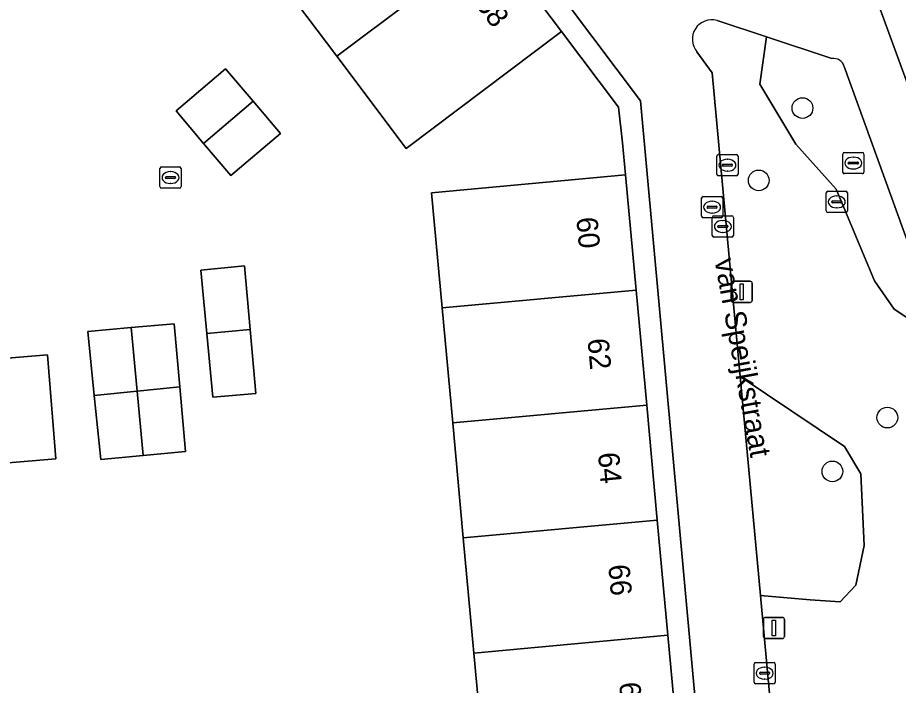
# Model space of a CAD drawing. Extents: x 160377 to 161131, y 383938 to 384853.
# Drawn here: x 160622.12 to 160663.69, y 384535.5 to 384567.01 of the extents above; entities that cross this region are included whole.
import ezdxf

# ---------------------------------------------------------------- set-up
doc = ezdxf.new("R2010")
doc.units = 0
for name, color, linetype in [('IMGEO_Boom', 7, 'Continuous'), ('IMGEO_Erf', 7, 'Continuous'), ('IMGEO_Groenvoorziening', 7, 'Continuous'), ('IMGEO_Kolk', 7, 'Continuous'), ('IMGEO_Lichtmast', 7, 'Continuous'), ('IMGEO_Openbare_ruimte_label', 7, 'Continuous'), ('IMGEO_Pand', 7, 'Continuous'), ('IMGEO_Pand_nummerreeks', 7, 'Continuous'), ('IMGEO_Rioolput', 7, 'Continuous'), ('IMGEO_Voetgangersgebied_open', 7, 'Continuous')]:
    doc.layers.add(name, color=color, linetype=linetype)

msp = doc.modelspace()

# ---------------------------------------------------------------- linework, layer by layer
at = {"layer": 'IMGEO_Boom'}
for centre in [(160659.166, 384562.744), (160657.1, 384559.33), (160663.171, 384548.138), (160660.578, 384545.599)]:
    msp.add_circle(centre, 0.489, dxfattribs=at)
at = {"layer": 'IMGEO_Erf'}
for points in [[(160656.048, 384504.315), (160656.893, 384504.376), (160651.516, 384563.083), (160634.758, 384585.358), (160611.972, 384615.646), (160608.482, 384613.028), (160596.383, 384603.983), (160593.555, 384601.453), (160592.642, 384600.679), (160589.954, 384598.377), (160589.048, 384597.617), (160586.272, 384595.285), (160585.368, 384594.478), (160578.674, 384588.862), (160588.469, 384577.392), (160609.42, 384552.826), (160611.199, 384533.452), (160614.226, 384500.488)], [(160742.043, 384557.929), (160741.675, 384559.771), (160712.316, 384578.736), (160711.06, 384579.547), (160690.284, 384592.968), (160678.608, 384600.475), (160670.645, 384605.594), (160652.047, 384589.687), (160648.865, 384586.974), (160652.625, 384581.692), (160662.829, 384567.417), (160665.29, 384560.709), (160670.064, 384547.52), (160670.583, 384546.086), (160681.057, 384517.15), (160682.984, 384507.279), (160717.593, 384514.044), (160723.481, 384515.195), (160749.399, 384520.262)], [(160629.603, 384562.612), (160631.936, 384564.59), (160633.234, 384563.069), (160634.532, 384561.547), (160632.184, 384559.557), (160630.9, 384561.077)], [(160631.054, 384552.1), (160630.774, 384555.098), (160632.834, 384555.303), (160633.101, 384552.29), (160633.369, 384549.277), (160631.333, 384549.101)], [(160627.479, 384552.382), (160629.508, 384552.567), (160629.776, 384549.584), (160630.051, 384546.531), (160628.049, 384546.342), (160626.047, 384546.153), (160625.741, 384549.174), (160625.434, 384552.196)]]:
    msp.add_lwpolyline(points, close=True, dxfattribs=at)
for points in [[(160621.611, 384601.175), (160624.884, 384596.822), (160628.157, 384592.469), (160631.431, 384588.116), (160634.704, 384583.762), (160637.977, 384579.409), (160641.25, 384575.056), (160644.524, 384570.703), (160647.791, 384566.349), (160650.487, 384562.787), (160650.671, 384561.096), (160650.813, 384559.589), (160651.313, 384554.154), (160651.813, 384548.726), (160652.312, 384543.297), (160652.811, 384537.869), (160653.311, 384532.44)], [(160644.155, 384531.6), (160643.656, 384537.028), (160643.158, 384542.457), (160642.659, 384547.885), (160642.161, 384553.314), (160641.662, 384558.742), (160650.813, 384559.589), (160650.671, 384561.096), (160650.487, 384562.787), (160647.791, 384566.349), (160640.461, 384560.832), (160637.187, 384565.185), (160633.913, 384569.537), (160630.639, 384573.89), (160627.365, 384578.243), (160624.091, 384582.595), (160620.818, 384586.948)], [(160619.944, 384550.806), (160623.524, 384551.103), (160623.931, 384546.19), (160620.351, 384545.893)]]:
    msp.add_lwpolyline(points, dxfattribs=at)
at = {"layer": 'IMGEO_Groenvoorziening'}
for points in [[(160657.46, 384566.101), (160655.132, 384566.872)], [(160674.853, 384526.804), (160665.84, 384551.711), (160663.489, 384553.259), (160662.566, 384554.598), (160660.752, 384558.915), (160658.847, 384561.034), (160657.157, 384563.866), (160657.46, 384566.101)], [(160660.553, 384565.076), (160657.46, 384566.101), (160657.157, 384563.866), (160658.847, 384561.034), (160660.752, 384558.915), (160662.566, 384554.598), (160663.489, 384553.259), (160665.84, 384551.711), (160661.136, 384564.711)], [(160654.184, 384565.394), (160654.909, 384564.413), (160656.229, 384550.075), (160661.151, 384546.774), (160661.917, 384545.486), (160662.071, 384542.104), (160661.684, 384540.236), (160660.94, 384539.438), (160659.532, 384539.533), (160657.181, 384539.738), (160659.169, 384518.154)]]:
    msp.add_lwpolyline(points, dxfattribs=at)
msp.add_lwpolyline([(160656.229, 384550.075), (160657.181, 384539.738), (160659.532, 384539.533), (160660.94, 384539.438), (160661.684, 384540.236), (160662.071, 384542.104), (160661.917, 384545.486), (160661.151, 384546.774)], close=True, dxfattribs=at)
for centre, radius, start, end in [((160654.886, 384565.987), 0.919, 74.4931, 220.1541), ((160660.636, 384564.56), 0.523, 16.8085, 99.0924)]:
    msp.add_arc(centre, radius, start, end, dxfattribs=at)
at = {"layer": 'IMGEO_Kolk'}
for p, q in [((160654.907, 384556.731), (160654.907, 384557.583)), ((160654.982, 384557.657), (160655.834, 384557.657)), ((160655.395, 384557.437), (160655.42, 384557.437)), ((160655.908, 384557.583), (160655.908, 384556.731)), ((160655.166, 384557.151), (160655.166, 384557.163)), ((160655.604, 384557.114), (160655.206, 384557.114)), ((160655.209, 384557.2), (160655.607, 384557.2)), ((160655.65, 384557.163), (160655.65, 384557.151)), ((160655.834, 384556.657), (160654.982, 384556.657)), ((160655.418, 384556.877), (160655.393, 384556.877)), ((160656.879, 384535.651), (160656.879, 384536.503)), ((160656.954, 384536.577), (160657.806, 384536.577)), ((160657.367, 384536.357), (160657.392, 384536.357)), ((160657.88, 384536.503), (160657.88, 384535.651)), ((160657.138, 384536.071), (160657.138, 384536.083)), ((160657.576, 384536.034), (160657.178, 384536.034)), ((160657.181, 384536.12), (160657.579, 384536.12)), ((160657.39, 384535.797), (160657.365, 384535.797)), ((160657.622, 384536.083), (160657.622, 384536.071)), ((160657.806, 384535.577), (160656.954, 384535.577))]:
    msp.add_line(p, q, dxfattribs=at)
for points in [[(160654.907, 384556.731), (160654.907, 384557.583)], [(160654.982, 384557.657), (160655.834, 384557.657)], [(160655.908, 384557.583), (160655.908, 384556.731)], [(160655.834, 384556.657), (160654.982, 384556.657)], [(160656.879, 384535.651), (160656.879, 384536.503)], [(160656.954, 384536.577), (160657.806, 384536.577)], [(160657.88, 384536.503), (160657.88, 384535.651)], [(160657.806, 384535.577), (160656.954, 384535.577)]]:
    msp.add_lwpolyline(points, dxfattribs=at)
for centre, radius, start, end in [((160654.984, 384557.581), 0.0765, 91.552, 178.448), ((160654.984, 384557.581), 0.0765, 91.552, 178.448), ((160655.832, 384557.581), 0.0765, 1.552, 88.448), ((160655.832, 384557.581), 0.0765, 1.552, 88.448), ((160655.206, 384557.16), 0.0403, 85.8775, 175.7526), ((160655.203, 384557.15), 0.0366, 178.938, 274.7102), ((160655.607, 384557.157), 0.043, 264.8664, 352.4533), ((160655.611, 384557.162), 0.0386, 1.7309, 96.639), ((160654.984, 384556.733), 0.0765, 181.552, 268.448), ((160654.984, 384556.733), 0.0765, 181.552, 268.448), ((160655.832, 384556.733), 0.0765, 271.552, 358.448), ((160655.832, 384556.733), 0.0765, 271.552, 358.448), ((160656.956, 384536.501), 0.0765, 91.552, 178.448), ((160656.956, 384536.501), 0.0765, 91.552, 178.448), ((160657.804, 384536.501), 0.0765, 1.552, 88.448), ((160657.804, 384536.501), 0.0765, 1.552, 88.448), ((160657.178, 384536.08), 0.0403, 85.8775, 175.7526), ((160657.175, 384536.07), 0.0366, 178.938, 274.7102), ((160657.579, 384536.077), 0.043, 264.8664, 352.4533), ((160657.583, 384536.082), 0.0386, 1.7309, 96.639), ((160656.956, 384535.653), 0.0765, 181.552, 268.448), ((160656.956, 384535.653), 0.0765, 181.552, 268.448), ((160657.804, 384535.653), 0.0765, 271.552, 358.448), ((160657.804, 384535.653), 0.0765, 271.552, 358.448)]:
    msp.add_arc(centre, radius, start, end, dxfattribs=at)
for centre, major_axis, ratio, start_param, end_param in [((160655.394, 384557.157), (-0.387, 0.002), 0.722429, 4.712389, 7.853982), ((160655.419, 384557.157), (-0.39, 0.002), 0.717154, 1.570796, 4.712389), ((160657.366, 384536.077), (-0.387, 0.002), 0.722429, 4.712389, 7.853982), ((160657.391, 384536.077), (-0.39, 0.002), 0.717154, 1.570796, 4.712389)]:
    msp.add_ellipse(centre, major_axis=major_axis, ratio=ratio, start_param=start_param, end_param=end_param, dxfattribs=at)
at = {"layer": 'IMGEO_Lichtmast'}
for p, q in [((160655.902, 384554.57), (160656.692, 384554.57)), ((160656.692, 384554.57), (160655.902, 384554.57)), ((160655.802, 384553.67), (160655.802, 384554.47)), ((160655.802, 384554.47), (160655.802, 384553.67)), ((160656.792, 384554.47), (160656.792, 384553.67)), ((160656.792, 384553.67), (160656.792, 384554.47)), ((160656.692, 384553.57), (160655.902, 384553.57)), ((160655.902, 384553.57), (160656.692, 384553.57)), ((160657.423, 384538.712), (160658.213, 384538.712)), ((160658.213, 384538.712), (160657.423, 384538.712)), ((160657.323, 384537.812), (160657.323, 384538.612)), ((160657.323, 384538.612), (160657.323, 384537.812)), ((160658.313, 384538.612), (160658.313, 384537.812)), ((160658.313, 384537.812), (160658.313, 384538.612)), ((160658.213, 384537.712), (160657.423, 384537.712)), ((160657.423, 384537.712), (160658.213, 384537.712))]:
    msp.add_line(p, q, dxfattribs=at)
for points in [[(160656.222, 384554.445), (160656.372, 384554.445), (160656.372, 384553.695), (160656.222, 384553.695), (160656.222, 384554.445)], [(160657.743, 384538.587), (160657.893, 384538.587), (160657.893, 384537.837), (160657.743, 384537.837), (160657.743, 384538.587)]]:
    msp.add_lwpolyline(points, dxfattribs=at)
for centre, start, end in [((160655.902, 384554.47), 90, 180), ((160655.902, 384554.47), 90, 180), ((160656.692, 384554.47), 0, 90), ((160656.692, 384554.47), 360, 90), ((160655.902, 384553.67), 180, 270), ((160655.902, 384553.67), 180, 270), ((160656.692, 384553.67), 270, 0), ((160656.692, 384553.67), 270, 0), ((160657.423, 384538.612), 90, 180), ((160657.423, 384538.612), 90, 180), ((160658.213, 384538.612), 0, 90), ((160658.213, 384538.612), 360, 90), ((160657.423, 384537.812), 180, 270), ((160657.423, 384537.812), 180, 270), ((160658.213, 384537.812), 270, 0), ((160658.213, 384537.812), 270, 0)]:
    msp.add_arc(centre, 0.1, start, end, dxfattribs=at)
at = {"layer": 'IMGEO_Pand'}
for points in [[(160644.524, 384570.703), (160641.25, 384575.056), (160633.913, 384569.537), (160637.187, 384565.185)], [(160647.791, 384566.349), (160644.524, 384570.703), (160637.187, 384565.185), (160640.461, 384560.832)], [(160633.234, 384563.069), (160631.936, 384564.59), (160629.603, 384562.612), (160630.9, 384561.077)], [(160634.532, 384561.547), (160633.234, 384563.069), (160630.9, 384561.077), (160632.184, 384559.557)], [(160650.813, 384559.589), (160641.662, 384558.742), (160642.161, 384553.314), (160651.313, 384554.154)], [(160630.774, 384555.098), (160631.054, 384552.1), (160633.101, 384552.29), (160632.834, 384555.303)], [(160651.313, 384554.154), (160642.161, 384553.314), (160642.659, 384547.885), (160651.813, 384548.726)], [(160627.479, 384552.382), (160627.762, 384549.38), (160629.776, 384549.584), (160629.508, 384552.567)], [(160627.479, 384552.382), (160625.434, 384552.196), (160625.741, 384549.174), (160627.762, 384549.38)], [(160633.101, 384552.29), (160631.054, 384552.1), (160631.333, 384549.101), (160633.369, 384549.277)], [(160619.944, 384550.806), (160610.483, 384549.847), (160610.541, 384549.275), (160610.755, 384549.291), (160611.166, 384544.854), (160614.454, 384545.127), (160620.374, 384545.619), (160620.351, 384545.893), (160623.931, 384546.19), (160623.524, 384551.103)], [(160629.776, 384549.584), (160627.762, 384549.38), (160628.049, 384546.342), (160630.051, 384546.531)], [(160627.762, 384549.38), (160625.741, 384549.174), (160626.047, 384546.153), (160628.049, 384546.342)], [(160651.813, 384548.726), (160642.659, 384547.885), (160643.158, 384542.457), (160652.312, 384543.297)], [(160652.312, 384543.297), (160643.158, 384542.457), (160643.656, 384537.028), (160652.811, 384537.869)], [(160652.811, 384537.869), (160643.656, 384537.028), (160644.155, 384531.6), (160653.311, 384532.44)]]:
    msp.add_lwpolyline(points, close=True, dxfattribs=at)
at = {"layer": 'IMGEO_Rioolput'}
for p, q in [((160655.124, 384559.622), (160655.124, 384560.474)), ((160655.199, 384560.548), (160656.051, 384560.548)), ((160655.612, 384560.328), (160655.637, 384560.328)), ((160656.125, 384560.474), (160656.125, 384559.622)), ((160661.064, 384559.722), (160661.064, 384560.574)), ((160661.139, 384560.648), (160661.991, 384560.648)), ((160661.552, 384560.428), (160661.577, 384560.428)), ((160662.065, 384560.574), (160662.065, 384559.722)), ((160628.837, 384559.038), (160628.837, 384559.89)), ((160628.912, 384559.964), (160629.764, 384559.964)), ((160629.838, 384559.89), (160629.838, 384559.038)), ((160655.383, 384560.042), (160655.383, 384560.054)), ((160655.821, 384560.005), (160655.423, 384560.005)), ((160655.426, 384560.091), (160655.824, 384560.091)), ((160655.867, 384560.054), (160655.867, 384560.042)), ((160661.323, 384560.142), (160661.323, 384560.154)), ((160661.761, 384560.105), (160661.363, 384560.105)), ((160661.366, 384560.191), (160661.764, 384560.191)), ((160661.807, 384560.154), (160661.807, 384560.142)), ((160629.139, 384559.507), (160629.537, 384559.507)), ((160629.325, 384559.744), (160629.35, 384559.744)), ((160656.051, 384559.548), (160655.199, 384559.548)), ((160655.635, 384559.768), (160655.61, 384559.768)), ((160661.991, 384559.648), (160661.139, 384559.648)), ((160661.575, 384559.868), (160661.55, 384559.868)), ((160629.096, 384559.458), (160629.096, 384559.47)), ((160629.534, 384559.421), (160629.136, 384559.421)), ((160629.348, 384559.184), (160629.323, 384559.184)), ((160629.58, 384559.47), (160629.58, 384559.458)), ((160629.764, 384558.964), (160628.912, 384558.964)), ((160660.286, 384557.89), (160660.286, 384558.742)), ((160660.361, 384558.816), (160661.213, 384558.816)), ((160661.287, 384558.742), (160661.287, 384557.89)), ((160654.402, 384557.641), (160654.402, 384558.493)), ((160654.477, 384558.567), (160655.329, 384558.567)), ((160654.89, 384558.347), (160654.915, 384558.347)), ((160655.403, 384558.493), (160655.403, 384557.641)), ((160660.545, 384558.31), (160660.545, 384558.322)), ((160660.983, 384558.273), (160660.585, 384558.273)), ((160660.588, 384558.359), (160660.986, 384558.359)), ((160660.774, 384558.596), (160660.799, 384558.596)), ((160661.029, 384558.322), (160661.029, 384558.31)), ((160654.661, 384558.061), (160654.661, 384558.073)), ((160655.099, 384558.024), (160654.701, 384558.024)), ((160654.704, 384558.11), (160655.102, 384558.11)), ((160655.145, 384558.073), (160655.145, 384558.061)), ((160661.213, 384557.816), (160660.361, 384557.816)), ((160660.797, 384558.036), (160660.772, 384558.036)), ((160655.329, 384557.567), (160654.477, 384557.567)), ((160654.913, 384557.787), (160654.888, 384557.787))]:
    msp.add_line(p, q, dxfattribs=at)
for points in [[(160655.124, 384559.622), (160655.124, 384560.474)], [(160655.199, 384560.548), (160656.051, 384560.548)], [(160656.125, 384560.474), (160656.125, 384559.622)], [(160661.064, 384559.722), (160661.064, 384560.574)], [(160661.139, 384560.648), (160661.991, 384560.648)], [(160662.065, 384560.574), (160662.065, 384559.722)], [(160628.837, 384559.038), (160628.837, 384559.89)], [(160628.912, 384559.964), (160629.764, 384559.964)], [(160629.838, 384559.89), (160629.838, 384559.038)], [(160656.051, 384559.548), (160655.199, 384559.548)], [(160661.991, 384559.648), (160661.139, 384559.648)], [(160629.764, 384558.964), (160628.912, 384558.964)], [(160660.286, 384557.89), (160660.286, 384558.742)], [(160660.361, 384558.816), (160661.213, 384558.816)], [(160661.287, 384558.742), (160661.287, 384557.89)], [(160654.402, 384557.641), (160654.402, 384558.493)], [(160654.477, 384558.567), (160655.329, 384558.567)], [(160655.403, 384558.493), (160655.403, 384557.641)], [(160661.213, 384557.816), (160660.361, 384557.816)], [(160655.329, 384557.567), (160654.477, 384557.567)]]:
    msp.add_lwpolyline(points, dxfattribs=at)
for centre, radius, start, end in [((160655.201, 384560.472), 0.0765, 91.552, 178.448), ((160655.201, 384560.472), 0.0765, 91.552, 178.448), ((160656.049, 384560.472), 0.0765, 1.552, 88.448), ((160656.049, 384560.472), 0.0765, 1.552, 88.448), ((160661.141, 384560.572), 0.0765, 91.552, 178.448), ((160661.141, 384560.572), 0.0765, 91.552, 178.448), ((160661.989, 384560.572), 0.0765, 1.552, 88.448), ((160661.989, 384560.572), 0.0765, 1.552, 88.448), ((160628.914, 384559.888), 0.0765, 91.552, 178.448), ((160628.914, 384559.888), 0.0765, 91.552, 178.448), ((160629.762, 384559.888), 0.0765, 1.552, 88.448), ((160629.762, 384559.888), 0.0765, 1.552, 88.448), ((160655.423, 384560.051), 0.0403, 85.8775, 175.7526), ((160655.42, 384560.041), 0.0366, 178.938, 274.7102), ((160655.824, 384560.048), 0.043, 264.8664, 352.4533), ((160655.828, 384560.053), 0.0386, 1.7309, 96.639), ((160661.363, 384560.151), 0.0403, 85.8775, 175.7526), ((160661.36, 384560.141), 0.0366, 178.938, 274.7102), ((160661.764, 384560.148), 0.043, 264.8664, 352.4533), ((160661.768, 384560.153), 0.0386, 1.7309, 96.639), ((160629.136, 384559.467), 0.0403, 85.8775, 175.7526), ((160629.541, 384559.469), 0.0386, 1.7309, 96.639), ((160655.201, 384559.624), 0.0765, 181.552, 268.448), ((160655.201, 384559.624), 0.0765, 181.552, 268.448), ((160656.049, 384559.624), 0.0765, 271.552, 358.448), ((160656.049, 384559.624), 0.0765, 271.552, 358.448), ((160661.141, 384559.724), 0.0765, 181.552, 268.448), ((160661.141, 384559.724), 0.0765, 181.552, 268.448), ((160661.989, 384559.724), 0.0765, 271.552, 358.448), ((160661.989, 384559.724), 0.0765, 271.552, 358.448), ((160629.133, 384559.457), 0.0366, 178.938, 274.7102), ((160629.537, 384559.464), 0.043, 264.8664, 352.4533), ((160628.914, 384559.04), 0.0765, 181.552, 268.448), ((160628.914, 384559.04), 0.0765, 181.552, 268.448), ((160629.762, 384559.04), 0.0765, 271.552, 358.448), ((160629.762, 384559.04), 0.0765, 271.552, 358.448), ((160660.363, 384558.74), 0.0765, 91.552, 178.448), ((160660.363, 384558.74), 0.0765, 91.552, 178.448), ((160661.211, 384558.74), 0.0765, 1.552, 88.448), ((160661.211, 384558.74), 0.0765, 1.552, 88.448), ((160654.479, 384558.491), 0.0765, 91.552, 178.448), ((160654.479, 384558.491), 0.0765, 91.552, 178.448), ((160655.327, 384558.491), 0.0765, 1.552, 88.448), ((160655.327, 384558.491), 0.0765, 1.552, 88.448), ((160660.585, 384558.319), 0.0403, 85.8775, 175.7526), ((160660.582, 384558.309), 0.0366, 178.938, 274.7102), ((160660.986, 384558.316), 0.043, 264.8664, 352.4533), ((160660.99, 384558.321), 0.0386, 1.7309, 96.639), ((160654.701, 384558.07), 0.0403, 85.8775, 175.7526), ((160654.698, 384558.06), 0.0366, 178.938, 274.7102), ((160655.102, 384558.067), 0.043, 264.8664, 352.4533), ((160655.106, 384558.072), 0.0386, 1.7309, 96.639), ((160660.363, 384557.892), 0.0765, 181.552, 268.448), ((160660.363, 384557.892), 0.0765, 181.552, 268.448), ((160661.211, 384557.892), 0.0765, 271.552, 358.448), ((160661.211, 384557.892), 0.0765, 271.552, 358.448), ((160654.479, 384557.643), 0.0765, 181.552, 268.448), ((160654.479, 384557.643), 0.0765, 181.552, 268.448), ((160655.327, 384557.643), 0.0765, 271.552, 358.448), ((160655.327, 384557.643), 0.0765, 271.552, 358.448)]:
    msp.add_arc(centre, radius, start, end, dxfattribs=at)
for centre, major_axis, ratio, start_param, end_param in [((160655.611, 384560.048), (-0.387, 0.002), 0.722429, 4.712389, 7.853982), ((160655.636, 384560.048), (-0.39, 0.002), 0.717154, 1.570796, 4.712389), ((160661.551, 384560.148), (-0.387, 0.002), 0.722429, 4.712389, 7.853982), ((160661.576, 384560.148), (-0.39, 0.002), 0.717154, 1.570796, 4.712389), ((160629.324, 384559.464), (-0.387, 0.002), 0.722429, 4.712389, 7.853982), ((160629.349, 384559.464), (-0.39, 0.002), 0.717154, 1.570796, 4.712389), ((160654.889, 384558.067), (-0.387, 0.002), 0.722429, 4.712389, 7.853982), ((160654.914, 384558.067), (-0.39, 0.002), 0.717154, 1.570796, 4.712389), ((160660.773, 384558.316), (-0.387, 0.002), 0.722429, 4.712389, 7.853982), ((160660.798, 384558.316), (-0.39, 0.002), 0.717154, 1.570796, 4.712389)]:
    msp.add_ellipse(centre, major_axis=major_axis, ratio=ratio, start_param=start_param, end_param=end_param, dxfattribs=at)
at = {"layer": 'IMGEO_Voetgangersgebied_open'}
for points in [[(160665.29, 384560.709), (160662.829, 384567.417), (160652.625, 384581.692), (160648.865, 384586.974), (160652.047, 384589.687), (160670.645, 384605.594), (160672.023, 384606.761), (160670.112, 384607.993), (160669.413, 384608.444), (160666.311, 384610.443), (160664.192, 384608.65), (160662.712, 384607.424), (160653.945, 384599.94), (160634.758, 384585.358), (160651.516, 384563.083), (160656.893, 384504.376), (160660.286, 384505.11), (160659.653, 384512.586)], [(160655.132, 384566.872), (160657.46, 384566.101), (160660.553, 384565.076)], [(160659.169, 384518.154), (160657.181, 384539.738), (160656.229, 384550.075), (160654.909, 384564.413), (160654.184, 384565.394)], [(160661.136, 384564.711), (160665.84, 384551.711)]]:
    msp.add_lwpolyline(points, dxfattribs=at)
for centre, radius, start, end in [((160654.886, 384565.987), 0.919, 74.4931, 220.1541), ((160660.636, 384564.56), 0.523, 16.8085, 99.0924)]:
    msp.add_arc(centre, radius, start, end, dxfattribs=at)

# ---------------------------------------------------------------- texts
at = {"layer": 'IMGEO_Openbare_ruimte_label'}
msp.add_text('van Speijkstraat', height=1, rotation=280.3663, dxfattribs=at).set_placement((160655.009, 384555.571))
at = {"layer": 'IMGEO_Pand_nummerreeks'}
for s, rotation, p in [('58', 306.9384, (160643.692, 384567.65)), ('60', 275.2595, (160648.489, 384557.561)), ('62', 275.2595, (160649.016, 384551.839)), ('64', 275.2595, (160649.511, 384546.461)), ('66', 275.2595, (160649.997, 384541.172)), ('68', 275.2595, (160650.508, 384535.619))]:
    msp.add_text(s, height=1, rotation=rotation, dxfattribs=at).set_placement(p)

doc.saveas('drawing.dxf')
